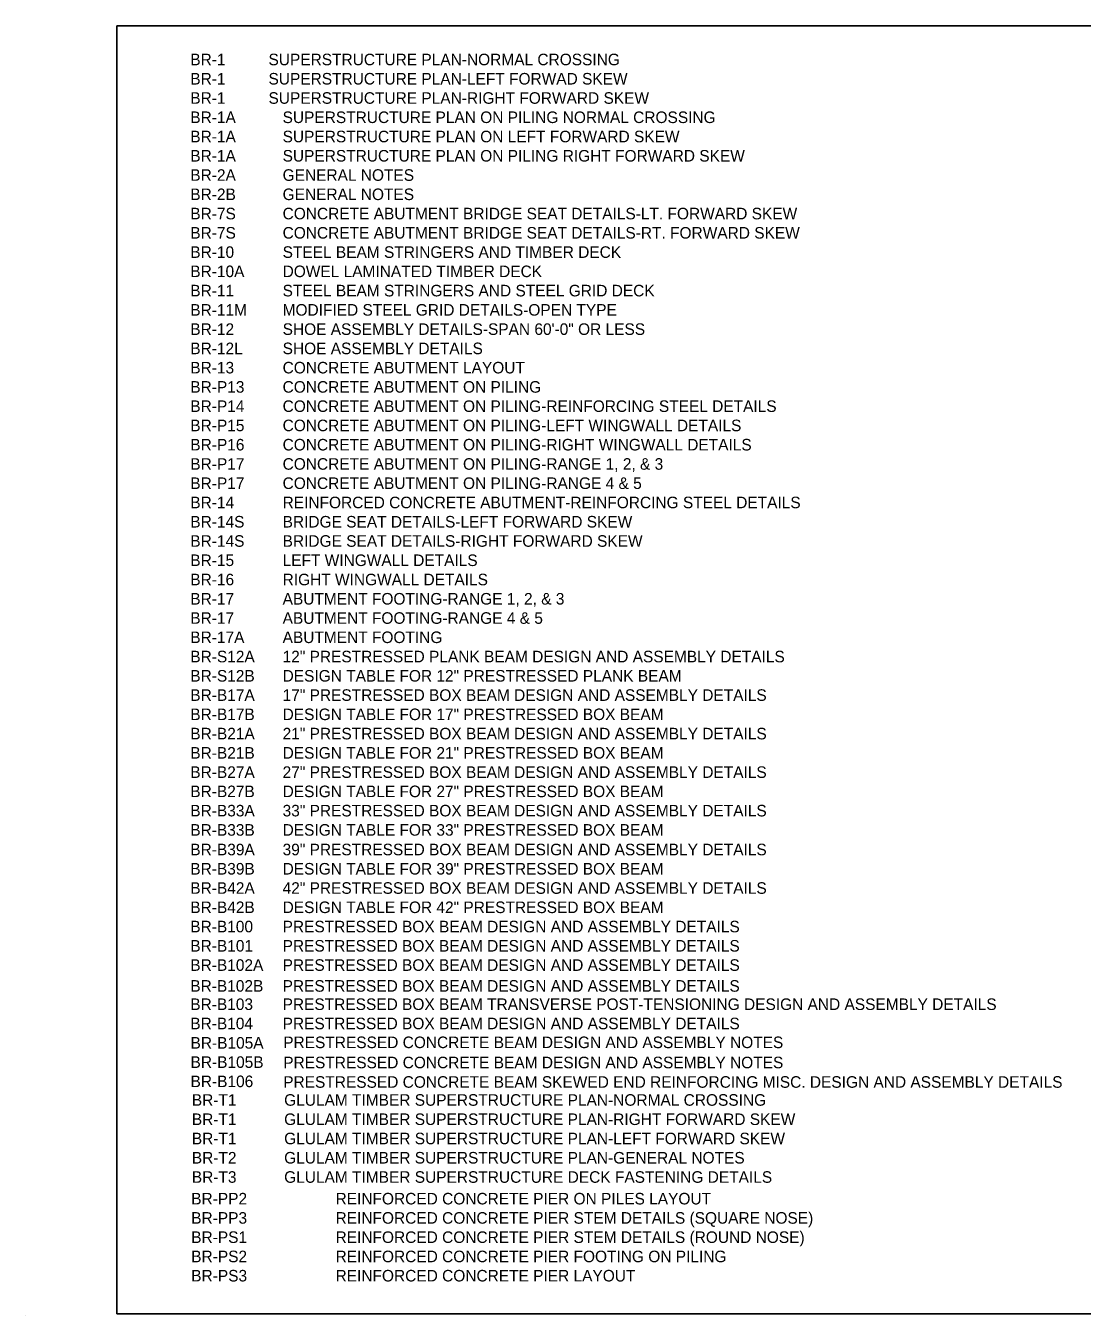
# Model space of a CAD drawing. Extents: x 4153 to 4683, y -1003 to -666.
# Drawn here: x 4153.4 to 4427.6, y -1002.6 to -667.8 of the extents above; entities that cross this region are included whole.
import ezdxf

# ---------------------------------------------------------------- set-up
doc = ezdxf.new("R2010")
doc.units = 0
for name, color, linetype in [('14', 7, 'Continuous'), ('63', 7, 'Continuous'), ('text', 7, 'Continuous')]:
    doc.layers.add(name, color=color, linetype=linetype)

msp = doc.modelspace()

# ---------------------------------------------------------------- linework, layer by layer
at = {"layer": '14'}
for p, q in [((4177.1, -667.82), (4177.07, -1002.22)), ((4177.1, -667.82), (4681.11, -667.84)), ((4681.1, -1002.24), (4177.07, -1002.22))]:
    msp.add_line(p, q, dxfattribs=at)
at = {"layer": '63'}
msp.add_line((4153.43, -1002.56), (4153.43, -1002.56), dxfattribs=at)

# ---------------------------------------------------------------- texts
at = {"layer": 'text'}
for s, height, p in [('BR-1          SUPERSTRUCTURE PLAN-NORMAL CROSSING', 3.0011, (4196.13, -678.07)), ('BR-1          SUPERSTRUCTURE PLAN-LEFT FORWAD SKEW', 3.0011, (4196.13, -683.07)), ('BR-1          SUPERSTRUCTURE PLAN-RIGHT FORWARD SKEW', 3.0011, (4196.13, -688.07)), ('BR-1A    ', 3.001, (4196.13, -693.07)), ('SUPERSTRUCTURE PLAN ON PILING NORMAL CROSSING', 3.0011, (4220.09, -693.07)), ('BR-1A', 3.001, (4196.13, -698.07)), ('SUPERSTRUCTURE PLAN ON LEFT FORWARD SKEW', 3.0011, (4220.09, -698.07)), ('BR-1A', 3.001, (4196.13, -703.07)), ('SUPERSTRUCTURE PLAN ON PILING RIGHT FORWARD SKEW', 3.0011, (4220.09, -703.07)), ('BR-2A', 3.001, (4196.13, -708.07)), ('GENERAL NOTES', 3.0011, (4220.09, -708.07)), ('BR-2B', 3.001, (4196.13, -713.07)), ('GENERAL NOTES', 3.0011, (4220.09, -713.07)), ('BR-7S', 3.001, (4196.13, -718.07)), ('CONCRETE ABUTMENT BRIDGE SEAT DETAILS-LT. FORWARD SKEW', 3.0011, (4220.09, -718.07)), ('BR-7S', 3.001, (4196.13, -723.07)), ('CONCRETE ABUTMENT BRIDGE SEAT DETAILS-RT. FORWARD SKEW', 3.0011, (4220.09, -723.07)), ('BR-10', 3.001, (4196.13, -728.07)), ('STEEL BEAM STRINGERS AND TIMBER DECK', 3.0011, (4220.09, -728.07)), ('BR-10A', 3.001, (4196.13, -733.07)), ('DOWEL LAMINATED TIMBER DECK', 3.0011, (4220.09, -733.07)), ('BR-11', 3.001, (4196.13, -738.07)), ('STEEL BEAM STRINGERS AND STEEL GRID DECK', 3.0011, (4220.09, -738.07)), ('BR-11M', 3.001, (4196.13, -743.07)), ('MODIFIED STEEL GRID DETAILS-OPEN TYPE', 3.0011, (4220.09, -743.07)), ('BR-12', 3.001, (4196.13, -748.07)), ('SHOE ASSEMBLY DETAILS-SPAN 60\'-0" OR LESS', 3.0011, (4220.09, -748.07)), ('BR-12L', 3.001, (4196.13, -753.07)), ('SHOE ASSEMBLY DETAILS', 3.0011, (4220.09, -753.07)), ('BR-13', 3.001, (4196.13, -758.07)), ('CONCRETE ABUTMENT LAYOUT', 3.0011, (4220.09, -758.07)), ('BR-P13', 3.001, (4196.13, -763.07)), ('CONCRETE ABUTMENT ON PILING', 3.0011, (4220.09, -763.07)), ('BR-P14', 3.001, (4196.13, -768.07)), ('CONCRETE ABUTMENT ON PILING-REINFORCING STEEL DETAILS', 3.0011, (4220.09, -768.07)), ('BR-P15', 3.001, (4196.13, -773.07)), ('CONCRETE ABUTMENT ON PILING-LEFT WINGWALL DETAILS', 3.0011, (4220.09, -773.07)), ('BR-P16', 3.001, (4196.13, -778.07)), ('CONCRETE ABUTMENT ON PILING-RIGHT WINGWALL DETAILS', 3.0011, (4220.09, -778.07)), ('BR-P17', 3.001, (4196.13, -783.07)), ('CONCRETE ABUTMENT ON PILING-RANGE 1, 2, & 3', 3.0011, (4220.09, -783.07)), ('BR-P17', 3.001, (4196.13, -788.07)), ('CONCRETE ABUTMENT ON PILING-RANGE 4 & 5', 3.0011, (4220.09, -788.07)), ('BR-14', 3.001, (4196.13, -793.07)), ('REINFORCED CONCRETE ABUTMENT-REINFORCING STEEL DETAILS', 3.0011, (4220.09, -793.07)), ('BR-14S', 3.001, (4196.13, -798.07)), ('BRIDGE SEAT DETAILS-LEFT FORWARD SKEW', 3.0011, (4220.09, -798.07)), ('BR-14S', 3.001, (4196.13, -803.07)), ('BRIDGE SEAT DETAILS-RIGHT FORWARD SKEW', 3.0011, (4220.09, -803.07)), ('BR-15', 3.001, (4196.13, -808.07)), ('LEFT WINGWALL DETAILS', 3.0011, (4220.09, -808.07)), ('BR-16', 3.001, (4196.13, -813.07)), ('RIGHT WINGWALL DETAILS', 3.0011, (4220.09, -813.07)), ('BR-17', 3.001, (4196.13, -818.07)), ('ABUTMENT FOOTING-RANGE 1, 2, & 3', 3.0011, (4220.09, -818.07)), ('BR-17', 3.001, (4196.13, -823.07)), ('ABUTMENT FOOTING-RANGE 4 & 5', 3.0011, (4220.09, -823.07)), ('BR-17A', 3.001, (4196.13, -828.07)), ('ABUTMENT FOOTING', 3.0011, (4220.09, -828.07)), ('BR-S12A', 3.001, (4196.13, -833.07)), ('12" PRESTRESSED PLANK BEAM DESIGN AND ASSEMBLY DETAILS', 3.0011, (4220.09, -833.07)), ('BR-S12B', 3.001, (4196.13, -838.07)), ('DESIGN TABLE FOR 12" PRESTRESSED PLANK BEAM', 3.0011, (4220.09, -838.07)), ('BR-B17A', 3.001, (4196.13, -843.07)), ('17" PRESTRESSED BOX BEAM DESIGN AND ASSEMBLY DETAILS', 3.0011, (4220.09, -843.07)), ('BR-B17B', 3.001, (4196.13, -848.07)), ('DESIGN TABLE FOR 17" PRESTRESSED BOX BEAM', 3.0011, (4220.09, -848.07)), ('BR-B21A', 3.001, (4196.13, -853.07)), ('21" PRESTRESSED BOX BEAM DESIGN AND ASSEMBLY DETAILS', 3.0011, (4220.09, -853.07)), ('BR-B21B', 3.001, (4196.13, -858.07)), ('DESIGN TABLE FOR 21" PRESTRESSED BOX BEAM', 3.0011, (4220.09, -858.07)), ('BR-B27A', 3.001, (4196.13, -863.07)), ('27" PRESTRESSED BOX BEAM DESIGN AND ASSEMBLY DETAILS', 3.0011, (4220.09, -863.07)), ('BR-B27B', 3.001, (4196.13, -868.07)), ('DESIGN TABLE FOR 27" PRESTRESSED BOX BEAM', 3.0011, (4220.09, -868.07)), ('BR-B33A', 3.001, (4196.13, -873.07)), ('33" PRESTRESSED BOX BEAM DESIGN AND ASSEMBLY DETAILS', 3.0011, (4220.09, -873.07)), ('BR-B33B', 3.001, (4196.13, -878.07)), ('DESIGN TABLE FOR 33" PRESTRESSED BOX BEAM', 3.0011, (4220.09, -878.07)), ('BR-B39A', 3.001, (4196.13, -883.16)), ('39" PRESTRESSED BOX BEAM DESIGN AND ASSEMBLY DETAILS', 3.0011, (4220.09, -883.16)), ('BR-B39B', 3.001, (4196.13, -888.16)), ('DESIGN TABLE FOR 39" PRESTRESSED BOX BEAM', 3.0011, (4220.09, -888.16)), ('BR-B42A', 3.001, (4196.13, -893.16)), ('42" PRESTRESSED BOX BEAM DESIGN AND ASSEMBLY DETAILS', 3.0011, (4220.09, -893.16)), ('BR-B42B', 3.001, (4196.13, -898.16)), ('DESIGN TABLE FOR 42" PRESTRESSED BOX BEAM', 3.0011, (4220.09, -898.16)), ('BR-B100', 3.001, (4196.13, -903.16)), ('PRESTRESSED BOX BEAM DESIGN AND ASSEMBLY DETAILS', 3.0011, (4220.09, -903.16)), ('BR-B101', 3.001, (4196.13, -908.16)), ('PRESTRESSED BOX BEAM DESIGN AND ASSEMBLY DETAILS', 3.0011, (4220.09, -908.16)), ('BR-B102A', 3.001, (4196.13, -913.16)), ('PRESTRESSED BOX BEAM DESIGN AND ASSEMBLY DETAILS', 3.0011, (4220.09, -913.16)), ('BR-B102B', 3.001, (4196.13, -918.57)), ('PRESTRESSED BOX BEAM DESIGN AND ASSEMBLY DETAILS', 3.0011, (4220.09, -918.57)), ('BR-B103', 3.001, (4196.13, -923.32)), ('PRESTRESSED BOX BEAM TRANSVERSE POST-TENSIONING DESIGN AND ASSEMBLY DETAILS', 3.0011, (4220.09, -923.32)), ('BR-B104', 3.001, (4196.13, -928.32)), ('PRESTRESSED BOX BEAM DESIGN AND ASSEMBLY DETAILS', 3.0011, (4220.09, -928.32)), ('BR-B105A', 3.001, (4196.19, -933.35)), ('PRESTRESSED CONCRETE BEAM DESIGN AND ASSEMBLY NOTES', 3.0011, (4220.25, -933.22)), ('BR-B105B', 3.001, (4196.19, -938.35)), ('PRESTRESSED CONCRETE BEAM DESIGN AND ASSEMBLY NOTES', 3.0011, (4220.25, -938.45)), ('BR-B106', 3.001, (4196.19, -943.35)), ('PRESTRESSED CONCRETE BEAM SKEWED END REINFORCING MISC. DESIGN AND ASSEMBLY DETAILS', 3.0011, (4220.25, -943.51)), ('BR-T1', 3.001, (4196.53, -948.18)), ('GLULAM TIMBER SUPERSTRUCTURE PLAN-NORMAL CROSSING', 3.0011, (4220.49, -948.18)), ('BR-T1', 3.001, (4196.53, -953.18)), ('GLULAM TIMBER SUPERSTRUCTURE PLAN-RIGHT FORWARD SKEW', 3.0011, (4220.49, -953.18)), ('BR-T1', 3.001, (4196.53, -958.18)), ('GLULAM TIMBER SUPERSTRUCTURE PLAN-LEFT FORWARD SKEW', 3.0011, (4220.49, -958.18)), ('BR-T2', 3.001, (4196.53, -963.18)), ('GLULAM TIMBER SUPERSTRUCTURE PLAN-GENERAL NOTES', 3.0011, (4220.49, -963.18)), ('BR-T3', 3.001, (4196.53, -968.18)), ('GLULAM TIMBER SUPERSTRUCTURE DECK FASTENING DETAILS', 3.0011, (4220.49, -968.18)), ('BR-PP2', 3.001, (4196.37, -973.8)), (' REINFORCED CONCRETE PIER ON PILES LAYOUT', 3.0011, (4232.72, -973.8)), ('BR-PP3', 3.001, (4196.37, -978.8)), (' REINFORCED CONCRETE PIER STEM DETAILS (SQUARE NOSE)', 3.0011, (4232.72, -978.8)), ('BR-PS1', 3.001, (4196.37, -983.8)), (' REINFORCED CONCRETE PIER STEM DETAILS (ROUND NOSE)', 3.0011, (4232.72, -983.8)), ('BR-PS2', 3.001, (4196.37, -988.8)), (' REINFORCED CONCRETE PIER FOOTING ON PILING', 3.0011, (4232.72, -988.8)), ('BR-PS3', 3.001, (4196.37, -993.8)), (' REINFORCED CONCRETE PIER LAYOUT', 3.0011, (4232.72, -993.8))]:
    msp.add_text(s, height=height, dxfattribs=at).set_placement(p)

doc.saveas('drawing.dxf')
